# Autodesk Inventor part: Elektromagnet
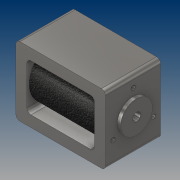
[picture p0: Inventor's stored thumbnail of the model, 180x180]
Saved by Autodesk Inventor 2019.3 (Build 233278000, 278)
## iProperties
Created: 2019-03
Part Number: Elektromagnet
Material: Ocel, legovaná
Document SubType Name: Modeling
Designer: B-hon
Density: 7.73 g/cm^3
Appearance: Pololeštěná
Author: B-hon
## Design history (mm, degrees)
sketch "Náčrt1"
  geometry: L1 (32.5, -25)-(-32.5, -25); L2 (-32.5, -25)-(-32.5, 25); L3 (-32.5, 25)-(32.5, 25); L4 (32.5, 25)-(32.5, -25); L5 (32.5, -25)-(-32.5, 25); L6 (-32.5, -25)-(32.5, 25); L7 (24.5, 17)-(-24.5, 17); L8 (-24.5, 17)-(-24.5, -17); L9 (-24.5, -17)-(24.5, -17); L10 (24.5, -17)-(24.5, 17); 1 further point
  constraints: 20 end point, 4 parallel, 2 midpoint, 2 perpendicular, 1 horizontal, 3 other
  dimensions: "d0" = 65 distance of L2.end L3.end; "d1" = 50 distance of L1.end L2.end; "d2" = 8 distance between parallel lines of L3 L7
extrude "Vysunutí1" new body sketch "Náčrt1" distance "d3" = 40; taper "d4" = 0 deg
fillet "Zaoblení1" dims "d5" = 3
sketch "Náčrt2"
  geometry: L1 (0, 44)-(0, 0) reference; L2 (-40, -3)-(0, -3) reference; C1 r 11.5 at (-20, 22); 1 further point
  constraints: 1 centre point
  dimensions: "d6" = 23 diameter of C1; "d7" = 20 distance from line of L1 C1.centre; "d8" = 25 distance from line of L2 C1.centre
extrude "Vysunutí2" join sketch "Náčrt2" distance "d9" = 2.5; taper "d10" = 0 deg
sketch "Náčrt3"
  geometry: C1 r 11.5 at (0, 0) reference; 2 further points
  constraints: 1 coincident
hole "Díra1" sketch "Náčrt3" at (0, 0) diameter "d11" = 6; stored, may be unused: countersink angle "d15" = 90 deg, drill point angle "d17" = 118 deg; dims "d12" = 6, "d13" = 8.7, "d14" = 2, "d16" = 15
sketch "Náčrt5"
  geometry: C1 r 3 at (-20, 14) reference; C2 r 18.5 at (-20, 14); 1 further point
  constraints: 1 centre point, 1 coincident
  dimensions: "d29" = 37 diameter of C2
extrude "Vysunutí3" join sketch "Náčrt5" distance "d30" = 49; taper "d31" = 0 deg
sketch "Náčrt6"
  geometry: C1 r 3 at (-20, 22) reference; 2 further points
  constraints: 1 vertical alignment
  dimensions: "d32" = 17 distance of point (-20, 39) C1.centre
hole "Díra3" sketch "Náčrt6" at (-20, 39) diameter "d33" = 3.242; stored, may be unused: countersink angle "d37" = 90 deg, drill point angle "d39" = 118 deg; dims "d34" = 8, "d35" = 4, "d36" = 2, "d38" = 11.8
pattern_circular "Kruhové pole2" dims angle "d41" = 360 deg
node "Těleso1"
